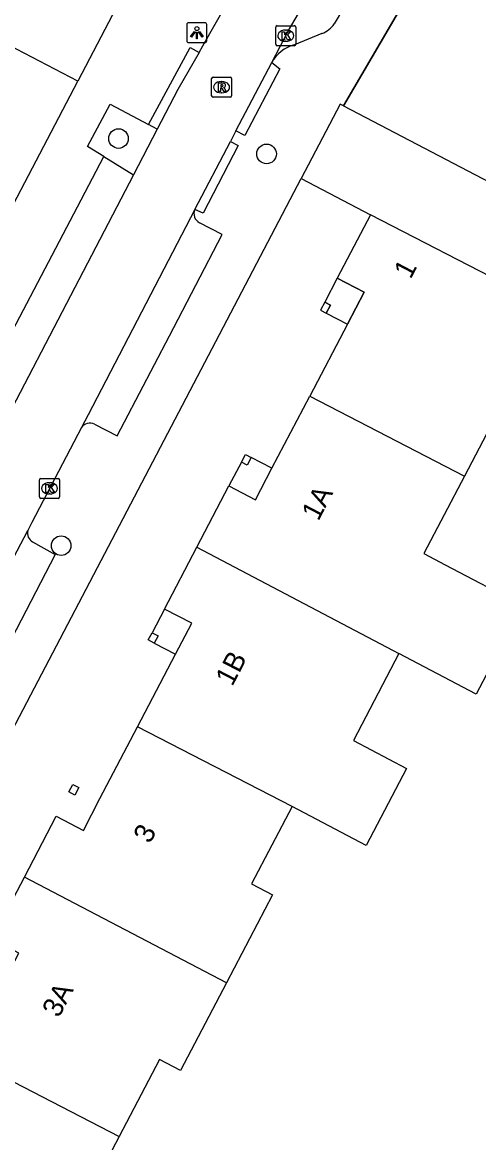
# Model space of a CAD drawing. Extents: x 160356 to 161355, y 381727 to 382845.
# Drawn here: x 160812.6 to 160835.4, y 382053.6 to 382109.5 of the extents above; entities that cross this region are included whole.
import ezdxf

# ---------------------------------------------------------------- set-up
doc = ezdxf.new("R2010")
doc.units = 0
for name, color, linetype in [('IMGEO_Boom', 7, 'Continuous'), ('IMGEO_Kolk', 7, 'Continuous'), ('IMGEO_Lichtpunt', 7, 'Continuous'), ('IMGEO_Muur', 7, 'Continuous'), ('IMGEO_Pand', 7, 'Continuous'), ('IMGEO_Pand_nummerreeks', 7, 'Continuous'), ('IMGEO_Pand_overbouw', 7, 'Continuous'), ('IMGEO_Parkeervlak_open', 7, 'Continuous'), ('IMGEO_Rijbaan_lokaal_open', 7, 'Continuous'), ('IMGEO_Rioolput', 7, 'Continuous'), ('IMGEO_Voetpad_halfverhard', 7, 'Continuous'), ('IMGEO_Voetpad_open', 7, 'Continuous')]:
    doc.layers.add(name, color=color, linetype=linetype)

msp = doc.modelspace()

# ---------------------------------------------------------------- linework, layer by layer
at = {"layer": 'IMGEO_Boom'}
for centre in [(160817.404, 382103.73), (160824.796, 382102.962), (160814.539, 382083.396)]:
    msp.add_circle(centre, 0.489, dxfattribs=at)
at = {"layer": 'IMGEO_Kolk'}
for p, q in [((160825.255, 382108.442), (160825.255, 382109.294)), ((160825.33, 382109.368), (160826.182, 382109.368)), ((160826.256, 382109.294), (160826.256, 382108.442)), ((160825.743, 382109.148), (160825.768, 382109.148)), ((160826.182, 382108.368), (160825.33, 382108.368)), ((160825.766, 382108.588), (160825.741, 382108.588)), ((160813.455, 382085.831), (160813.455, 382086.683)), ((160813.53, 382086.757), (160814.382, 382086.757)), ((160813.943, 382086.537), (160813.968, 382086.537)), ((160814.456, 382086.683), (160814.456, 382085.831)), ((160814.382, 382085.757), (160813.53, 382085.757)), ((160813.966, 382085.977), (160813.941, 382085.977))]:
    msp.add_line(p, q, dxfattribs=at)
for points in [[(160825.255, 382108.442), (160825.255, 382109.294)], [(160825.33, 382109.368), (160826.182, 382109.368)], [(160826.256, 382109.294), (160826.256, 382108.442)], [(160825.576, 382109.068), (160825.699, 382109.068), (160825.699, 382108.917), (160825.829, 382109.068), (160825.993, 382109.068), (160825.847, 382108.917), (160826, 382108.668), (160825.848, 382108.668), (160825.763, 382108.832), (160825.699, 382108.765), (160825.699, 382108.668), (160825.576, 382108.668), (160825.576, 382109.068)], [(160826.182, 382108.368), (160825.33, 382108.368)], [(160813.455, 382085.831), (160813.455, 382086.683)], [(160813.53, 382086.757), (160814.382, 382086.757)], [(160813.776, 382086.457), (160813.899, 382086.457), (160813.899, 382086.306), (160814.029, 382086.457), (160814.193, 382086.457), (160814.047, 382086.306), (160814.2, 382086.057), (160814.048, 382086.057), (160813.963, 382086.221), (160813.899, 382086.154), (160813.899, 382086.057), (160813.776, 382086.057), (160813.776, 382086.457)], [(160814.456, 382086.683), (160814.456, 382085.831)], [(160814.382, 382085.757), (160813.53, 382085.757)]]:
    msp.add_lwpolyline(points, dxfattribs=at)
for centre, start, end in [((160825.332, 382109.292), 91.552, 178.448), ((160825.332, 382109.292), 91.552, 178.448), ((160826.18, 382109.292), 1.552, 88.448), ((160826.18, 382109.292), 1.552, 88.448), ((160825.332, 382108.444), 181.552, 268.448), ((160825.332, 382108.444), 181.552, 268.448), ((160826.18, 382108.444), 271.552, 358.448), ((160826.18, 382108.444), 271.552, 358.448), ((160813.532, 382086.681), 91.552, 178.448), ((160813.532, 382086.681), 91.552, 178.448), ((160814.38, 382086.681), 1.552, 88.448), ((160814.38, 382086.681), 1.552, 88.448), ((160813.532, 382085.833), 181.552, 268.448), ((160813.532, 382085.833), 181.552, 268.448), ((160814.38, 382085.833), 271.552, 358.448), ((160814.38, 382085.833), 271.552, 358.448)]:
    msp.add_arc(centre, 0.0765, start, end, dxfattribs=at)
for centre, major_axis, ratio, start_param, end_param in [((160825.742, 382108.868), (-0.387, 0.002), 0.722429, 4.712389, 7.853982), ((160825.767, 382108.868), (-0.39, 0.002), 0.717154, 1.570796, 4.712389), ((160813.942, 382086.257), (-0.387, 0.002), 0.722429, 4.712389, 7.853982), ((160813.967, 382086.257), (-0.39, 0.002), 0.717154, 1.570796, 4.712389)]:
    msp.add_ellipse(centre, major_axis=major_axis, ratio=ratio, start_param=start_param, end_param=end_param, dxfattribs=at)
at = {"layer": 'IMGEO_Lichtpunt'}
for p, q in [((160820.816, 382109.421), (160820.816, 382108.614)), ((160820.816, 382109.421), (160820.816, 382108.614)), ((160821.718, 382109.516), (160820.91, 382109.516)), ((160821.718, 382109.516), (160820.91, 382109.516)), ((160821.812, 382108.614), (160821.812, 382109.421)), ((160821.812, 382108.614), (160821.812, 382109.421)), ((160820.91, 382108.52), (160821.718, 382108.52)), ((160820.91, 382108.52), (160821.718, 382108.52))]:
    msp.add_line(p, q, dxfattribs=at)
for points in [[(160821.19, 382109.085), (160821.229, 382109.057), (160821.041, 382108.795), (160821.003, 382108.822), (160821.19, 382109.085)], [(160821.292, 382109.037), (160821.339, 382109.037), (160821.339, 382108.715), (160821.292, 382108.715), (160821.292, 382109.037)], [(160821.402, 382109.057), (160821.44, 382109.084), (160821.627, 382108.822), (160821.588, 382108.794), (160821.402, 382109.057)]]:
    msp.add_lwpolyline(points, dxfattribs=at)
msp.add_circle((160821.315, 382109.219), 0.0994, dxfattribs=at)
for centre, start, end in [((160820.91, 382109.421), 90, 180), ((160820.91, 382109.421), 90, 180), ((160821.718, 382109.421), 0, 90), ((160821.718, 382109.421), 0, 90), ((160820.91, 382108.614), 180, 270), ((160820.91, 382108.614), 180, 270), ((160821.718, 382108.614), 270, 0), ((160821.718, 382108.614), 270, 360)]:
    msp.add_arc(centre, 0.0946, start, end, dxfattribs=at)
at = {"layer": 'IMGEO_Muur'}
msp.add_lwpolyline([(160828.644, 382105.359), (160835.677, 382117.417)], dxfattribs=at)
at = {"layer": 'IMGEO_Pand'}
for points in [[(160828.644, 382105.359), (160828.467, 382105.452), (160826.52, 382101.729)], [(160828.644, 382105.359), (160839.235, 382099.82)], [(160826.52, 382101.729), (160829.984, 382099.917)], [(160829.984, 382099.917), (160828.329, 382096.753), (160829.665, 382096.055), (160828.832, 382094.462), (160826.953, 382090.869)], [(160837.1, 382096.26), (160829.984, 382099.917)], [(160827.987, 382095.407), (160827.703, 382095.556), (160827.496, 382095.16), (160827.78, 382095.012), (160827.987, 382095.407)], [(160840.049, 382094.652), (160837.714, 382090.187), (160836.694, 382090.72), (160834.676, 382086.862)], [(160821.314, 382083.315), (160822.918, 382086.381), (160824.243, 382085.688), (160825.065, 382087.259), (160826.953, 382090.869)], [(160826.953, 382090.869), (160834.676, 382086.862)], [(160823.54, 382087.57), (160823.739, 382087.95), (160824.025, 382087.8), (160823.826, 382087.42), (160823.54, 382087.57)], [(160834.676, 382086.862), (160832.655, 382082.997), (160833.72, 382082.44), (160837.592, 382080.403), (160835.263, 382075.977), (160831.402, 382078.008)], [(160818.349, 382074.341), (160820.249, 382077.974), (160821.058, 382079.522), (160819.702, 382080.232), (160821.314, 382083.315)], [(160821.314, 382083.315), (160831.402, 382078.008)], [(160818.891, 382078.685), (160819.079, 382079.046), (160819.38, 382078.888), (160819.192, 382078.528), (160818.891, 382078.685)], [(160831.402, 382078.008), (160829.132, 382073.668), (160831.791, 382072.269), (160829.768, 382068.424), (160826.069, 382070.37)], [(160812.701, 382066.846), (160814.29, 382069.884), (160815.647, 382069.175), (160816.477, 382070.761), (160818.349, 382074.341)], [(160826.069, 382070.37), (160818.349, 382074.341)], [(160815.418, 382071.313), (160815.221, 382070.936), (160814.922, 382071.092), (160815.119, 382071.469), (160815.418, 382071.313)], [(160826.069, 382070.37), (160824.05, 382066.51), (160825.096, 382065.963), (160822.794, 382061.562)], [(160809.727, 382057.872), (160811.811, 382061.857), (160812.433, 382063.047), (160811.083, 382063.753), (160812.701, 382066.846)], [(160822.794, 382061.562), (160812.701, 382066.846)], [(160822.794, 382061.562), (160820.506, 382057.187), (160819.452, 382057.738), (160817.44, 382053.89)], [(160809.727, 382057.872), (160817.44, 382053.89)], [(160817.44, 382053.89), (160815.422, 382050.032), (160816.463, 382049.487), (160814.096, 382044.962)]]:
    msp.add_lwpolyline(points, dxfattribs=at)
at = {"layer": 'IMGEO_Pand_overbouw'}
for points in [[(160829.665, 382096.055), (160828.329, 382096.753), (160827.703, 382095.556), (160827.987, 382095.407), (160827.78, 382095.012), (160828.832, 382094.462)], [(160825.065, 382087.259), (160824.025, 382087.8), (160823.826, 382087.42), (160823.54, 382087.57), (160822.918, 382086.381), (160824.243, 382085.688)], [(160819.079, 382079.046), (160819.38, 382078.888), (160819.192, 382078.528), (160820.249, 382077.974), (160821.058, 382079.522), (160819.702, 382080.232)]]:
    msp.add_lwpolyline(points, close=True, dxfattribs=at)
at = {"layer": 'IMGEO_Parkeervlak_open'}
msp.add_lwpolyline([(160816.678, 382102.83), (160818.149, 382101.922)], dxfattribs=at)
at = {"layer": 'IMGEO_Rijbaan_lokaal_open'}
for points in [[(160825.053, 382107.525), (160825.888, 382109.122), (160830.73, 382117.391)], [(160821.424, 382108.034), (160821.61, 382108.36), (160822.844, 382110.527)], [(160821.424, 382108.034), (160820.371, 382106.185), (160819.334, 382104.195)], [(160823.266, 382104.109), (160825.053, 382107.525)], [(160819.334, 382104.195), (160818.149, 382101.922)], [(160823.266, 382104.109), (160822.991, 382103.583)], [(160821.211, 382100.185), (160822.991, 382103.583)], [(160818.149, 382101.922), (160808.496, 382083.401), (160794.187, 382056.116), (160791.683, 382051.339)], [(160821.211, 382100.185), (160815.882, 382089.93), (160815.548, 382089.292)], [(160815.548, 382089.292), (160813.067, 382084.559), (160812.927, 382084.26), (160812.87, 382084.152)], [(160807.247, 382073.463), (160812.87, 382084.152)]]:
    msp.add_lwpolyline(points, dxfattribs=at)
at = {"layer": 'IMGEO_Rioolput'}
for p, q in [((160822.05, 382105.869), (160822.05, 382106.721)), ((160822.125, 382106.795), (160822.977, 382106.795)), ((160822.538, 382106.575), (160822.563, 382106.575)), ((160823.051, 382106.721), (160823.051, 382105.869)), ((160822.561, 382106.015), (160822.536, 382106.015)), ((160822.977, 382105.795), (160822.125, 382105.795))]:
    msp.add_line(p, q, dxfattribs=at)
for points in [[(160822.05, 382105.869), (160822.05, 382106.721)], [(160822.125, 382106.795), (160822.977, 382106.795)], [(160822.639, 382106.493), (160822.387, 382106.495), (160822.387, 382106.095)], [(160823.051, 382106.721), (160823.051, 382105.869)], [(160822.387, 382106.095), (160822.511, 382106.095), (160822.511, 382106.257), (160822.522, 382106.257)], [(160822.565, 382106.414), (160822.511, 382106.414), (160822.511, 382106.333)], [(160822.511, 382106.333), (160822.563, 382106.333)], [(160822.569, 382106.228), (160822.64, 382106.095), (160822.78, 382106.095), (160822.715, 382106.221)], [(160822.977, 382105.795), (160822.125, 382105.795)]]:
    msp.add_lwpolyline(points, dxfattribs=at)
for centre, radius, start, end in [((160822.127, 382106.719), 0.0765, 91.552, 178.448), ((160822.127, 382106.719), 0.0765, 91.552, 178.448), ((160822.638, 382106.383), 0.109, 350.3612, 89.416), ((160822.975, 382106.719), 0.0765, 1.552, 88.448), ((160822.975, 382106.719), 0.0765, 1.552, 88.448), ((160822.127, 382105.871), 0.0765, 181.552, 268.448), ((160822.127, 382105.871), 0.0765, 181.552, 268.448), ((160822.521, 382106.204), 0.0533, 26.0293, 88.6989), ((160822.547, 382106.522), 0.19, 274.7715, 282.9687), ((160822.571, 382106.318), 0.0964, 77.0061, 93.1865), ((160822.585, 382106.375), 0.0378, 276.6634, 79.6772), ((160822.636, 382106.383), 0.112, 277.5842, 350.9817), ((160822.62, 382106.168), 0.108, 29.5134, 73.7905), ((160822.975, 382105.871), 0.0765, 271.552, 358.448), ((160822.975, 382105.871), 0.0765, 271.552, 358.448)]:
    msp.add_arc(centre, radius, start, end, dxfattribs=at)
for centre, major_axis, ratio, start_param, end_param in [((160822.537, 382106.295), (-0.387, 0.002), 0.722429, 4.712389, 7.853982), ((160822.562, 382106.295), (-0.39, 0.002), 0.717154, 1.570796, 4.712389)]:
    msp.add_ellipse(centre, major_axis=major_axis, ratio=ratio, start_param=start_param, end_param=end_param, dxfattribs=at)
at = {"layer": 'IMGEO_Voetpad_halfverhard'}
msp.add_lwpolyline([(160815.372, 382106.589), (160811.933, 382108.388)], dxfattribs=at)
at = {"layer": 'IMGEO_Voetpad_open'}
for points in [[(160842.749, 382129.543), (160835.677, 382117.417), (160828.644, 382105.359)], [(160830.969, 382114.176), (160828.175, 382109.465)], [(160817.137, 382109.957), (160817.107, 382109.905), (160815.372, 382106.589)], [(160827.56, 382108.973), (160826.185, 382108.417)], [(160818.896, 382104.43), (160820.985, 382108.272), (160821.424, 382108.034)], [(160825.053, 382107.525), (160825.456, 382107.217), (160823.709, 382103.877), (160823.266, 382104.109)], [(160750, 381983.553), (160751.631, 381984.178), (160759.835, 382000), (160785.858, 382050.188), (160815.372, 382106.589)], [(160816.678, 382102.83), (160815.852, 382103.339), (160816.986, 382105.454), (160818.896, 382104.43)], [(160819.334, 382104.195), (160818.896, 382104.43)], [(160822.991, 382103.583), (160823.38, 382103.379), (160821.639, 382100), (160821.211, 382100.185)], [(160811.199, 382092.411), (160815.347, 382100.318), (160816.678, 382102.83)], [(160800.514, 382052.05), (160800.981, 382052.95), (160826.52, 382101.729)], [(160816.208, 382089.468), (160817.337, 382088.882), (160817.7, 382089.575), (160819.954, 382093.882), (160822.583, 382098.937), (160821.446, 382099.527)], [(160813.116, 382083.585), (160814.238, 382082.954), (160809.128, 382073.122), (160807.933, 382073.686)]]:
    msp.add_lwpolyline(points, dxfattribs=at)
for centre, radius, start, end in [((160827.1, 382110.179), 1.291, 290.8978, 326.4218), ((160826.68, 382106.624), 1.86, 105.446, 151.0292), ((160821.682, 382099.982), 0.513, 156.7068, 242.6008), ((160815.982, 382088.991), 0.528, 64.6138, 145.249), ((160813.364, 382084.029), 0.509, 166.0595, 240.849)]:
    msp.add_arc(centre, radius, start, end, dxfattribs=at)

# ---------------------------------------------------------------- texts
at = {"layer": 'IMGEO_Pand_nummerreeks'}
for s, rotation, p in [('1', 62.3894, (160831.989, 382096.672)), ('1A', 62.4973, (160827.383, 382084.591)), ('1B', 62.511, (160823.082, 382076.329)), ('3', 62.3323, (160818.977, 382068.472)), ('3A', 62.3909, (160814.423, 382059.774))]:
    msp.add_text(s, height=1, rotation=rotation, dxfattribs=at).set_placement(p)

doc.saveas('drawing.dxf')
